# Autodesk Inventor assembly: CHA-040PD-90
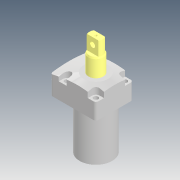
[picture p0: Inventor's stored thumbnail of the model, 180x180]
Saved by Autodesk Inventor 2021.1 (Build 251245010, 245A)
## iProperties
Created: 2018-12
Part Number: CHA-040PD-90
Description: STEP AP214
Document SubType Name: Assembly
Designer: user
Title: CHA-040PD-90.STEP
Revision Number: ÈÎºÎ
Sending System: SolidWorks 2016
Preprocessor: SwSTEP 2.0
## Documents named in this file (4)
- D:\Vault_2016\Projekty\Clamptek\Hydraulic\CHA-P\Inventor\CHA-040PD-90\CHA-040PD-90.iam
- D:\Vault_2016\Projekty\Clamptek\Hydraulic\CHA-P\Inventor\CHA-040PD-90\CHA-040P(BT).ipt
- D:\Vault_2016\Projekty\Clamptek\Hydraulic\CHA-P\Inventor\CHA-040PD-90\¶ÂÍ·G8-1.ipt
- D:\Vault_2016\Projekty\Clamptek\Hydraulic\CHA-P\Inventor\CHA-040PD-90\CHA-040PD»îÈû¸Ë.ipt
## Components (4 placed, 4 different names)
1. CHA-040P(BT)_1
2. ¶ÂÍ·G8-1_2
3. ¶ÂÍ·G8-1_3
4. CHA-040PD»îÈû¸Ë_4
